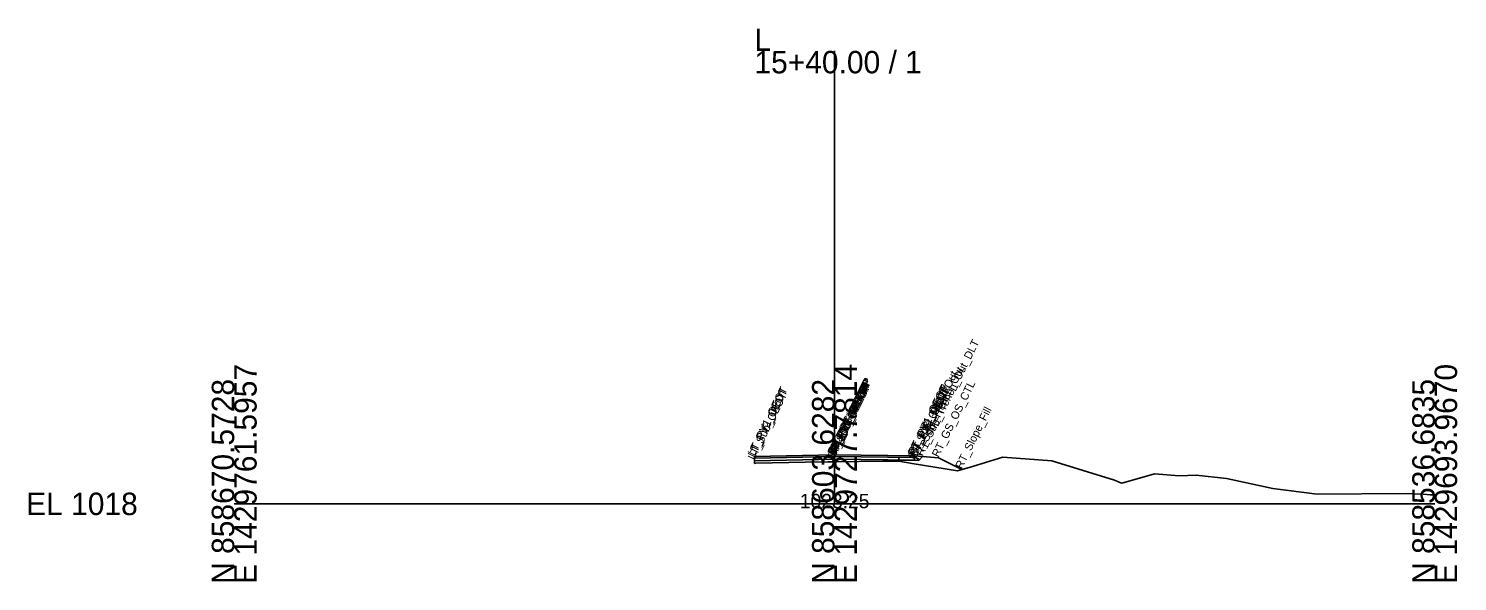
# Model space of a CAD drawing. Extents: x -26 to 2303, y -10 to 19558.
# Drawn here: x 2124.3 to 2302.8, y 5490.3 to 5559.4 of the extents above; entities that cross this region are included whole.
import ezdxf

# ---------------------------------------------------------------- set-up
doc = ezdxf.new("R2010")
doc.units = 0
for name, color, linetype in [('Default', 7, 'Continuous'), ('Exist Cross Section Cell', 7, 'Continuous'), ('Exist XS Center Line Elevation Label', 7, 'Continuous'), ('Exist XS Ground Line', 7, 'Continuous'), ('Prop CMT Conc Surface', 7, 'Continuous'), ('Prop CMT Pvmt Course 1', 7, 'Continuous'), ('Prop CMT Pvmt Course 2', 7, 'Continuous'), ('Prop CMT Pvmt Surface', 7, 'Continuous'), ('Prop CMT Pvmt Surface Shoulder', 7, 'Continuous'), ('Prop CMT Shld Paved Course 1', 7, 'Continuous'), ('Prop CMT Shld Paved Course 2', 7, 'Continuous'), ('Prop CMT Slope Grass', 7, 'Continuous'), ('Prop CMT Subgrade Earthwork', 7, 'Continuous'), ('Prop XS Dump Level', 7, 'Continuous')]:
    doc.layers.add(name, color=color, linetype=linetype)

msp = doc.modelspace()

# ---------------------------------------------------------------- linework, layer by layer
at = {"layer": 'Exist Cross Section Cell'}
for p, q in [((2225, 5500), (2225, 5556.59)), ((2150, 5500), (2225, 5500)), ((2225, 5500), (2300, 5500))]:
    msp.add_line(p, q, dxfattribs=at)
at = {"layer": 'Exist XS Ground Line'}
msp.add_lwpolyline([(2215, 5505.05), (2215.17, 5505.07), (2221.33, 5505.19), (2224.16, 5505.24), (2225, 5505.25), (2231.03, 5505.33), (2233.05, 5505.35), (2234.71, 5505.03), (2240.36, 5504.12), (2241.26, 5504.37), (2242.26, 5504.65), (2246.02, 5505.85), (2252.16, 5505.36), (2260.01, 5502.97), (2260.86, 5502.57), (2261.67, 5502.79), (2265.01, 5503.74), (2268.09, 5503.48), (2270.2, 5503.59), (2274, 5503.16), (2279.79, 5501.92), (2285.33, 5501.23), (2296.45, 5501.28), (2298.57, 5501.19), (2299.42, 5501.13), (2300, 5501.11)], dxfattribs=at)
at = {"layer": 'Prop CMT Conc Surface'}
for p, q in [((2215, 5505.39), (2215, 5505.05)), ((2233.05, 5505.35), (2233.05, 5505.81))]:
    msp.add_line(p, q, dxfattribs=at)
at = {"layer": 'Prop CMT Pvmt Course 1'}
for points in [[(2225, 5506.13), (2215, 5505.93)], [(2225, 5505.92), (2225, 5506.13)], [(2225, 5506.13), (2235, 5505.99)], [(2225, 5505.92), (2225, 5506.13)], [(2235, 5505.99), (2235, 5505.78)], [(2215, 5505.93), (2215, 5505.72)], [(2215, 5505.72), (2225, 5505.92)], [(2235, 5505.78), (2225, 5505.92)]]:
    msp.add_lwpolyline(points, dxfattribs=at)
msp.add_lwpolyline([(2225, 5505.92), (2225, 5506), (2225, 5506), (2225, 5505.92)], close=True, dxfattribs=at)
msp.add_lwpolyline([(2225, 5505.92), (2225, 5506), (2225, 5506), (2225, 5505.92)], close=True, dxfattribs=at)
at = {"layer": 'Prop CMT Pvmt Course 2'}
for points in [[(2225, 5505.92), (2215, 5505.72)], [(2215, 5505.72), (2215, 5505.39)], [(2225, 5505.92), (2235, 5505.78)], [(2235, 5505.45), (2233.05, 5505.47)], [(2235, 5505.78), (2235, 5505.45)]]:
    msp.add_lwpolyline(points, dxfattribs=at)
at = {"layer": 'Prop CMT Pvmt Surface'}
for points in [[(2225, 5506.13), (2215, 5505.93)], [(2225, 5506.13), (2235, 5505.99)]]:
    msp.add_lwpolyline(points, dxfattribs=at)
at = {"layer": 'Prop CMT Pvmt Surface Shoulder'}
msp.add_lwpolyline([(2235, 5505.99), (2235, 5505.99)], dxfattribs=at)
at = {"layer": 'Prop CMT Shld Paved Course 1'}
for points in [[(2235, 5505.99), (2235, 5505.99)], [(2235, 5505.99), (2235.21, 5505.77)], [(2235, 5505.78), (2235, 5505.99)], [(2235.21, 5505.77), (2235, 5505.78)]]:
    msp.add_lwpolyline(points, dxfattribs=at)
at = {"layer": 'Prop CMT Shld Paved Course 2'}
for points in [[(2235, 5505.78), (2235.21, 5505.77)], [(2235, 5505.45), (2235, 5505.78)], [(2235.55, 5505.43), (2235, 5505.45)], [(2235.21, 5505.77), (2235.21, 5505.77)], [(2235.21, 5505.77), (2235.55, 5505.43)]]:
    msp.add_lwpolyline(points, dxfattribs=at)
at = {"layer": 'Prop CMT Slope Grass'}
msp.add_lwpolyline([(2235, 5505.99), (2238, 5505.75), (2240.93, 5504.28)], dxfattribs=at)
at = {"layer": 'Prop CMT Subgrade Earthwork'}
for points in [[(2225, 5505.59), (2215, 5505.39)], [(2225, 5505.59), (2235, 5505.45)], [(2235, 5505.45), (2235.55, 5505.43)], [(2235.55, 5505.43), (2236.02, 5505.91)]]:
    msp.add_lwpolyline(points, dxfattribs=at)

# ---------------------------------------------------------------- texts
at = {"layer": 'Default'}
msp.add_text('-', height=0.0001, dxfattribs=at).set_placement((2150, 5500))
at = {"layer": 'Exist Cross Section Cell'}
for s, p in [('L', (2215, 5556.59)), ('15+40.00 / 1', (2215, 5553.79)), ('EL 1018', (2124, 5498.6))]:
    msp.add_text(s, height=2.8, dxfattribs=at).set_placement(p)
for s, p in [('E 1429761.5957', (2152.8, 5490)), ('E 1429727.7814', (2227.8, 5490)), ('E 1429693.9670', (2302.8, 5490)), ('N 858670.5728', (2150, 5490)), ('N 858603.6282', (2225, 5490)), ('N 858536.6835', (2300, 5490))]:
    msp.add_text(s, height=2.8, rotation=90, dxfattribs=at).set_placement(p)
at = {"layer": 'Exist XS Center Line Elevation Label'}
msp.add_text('1023.25', height=1.8, dxfattribs=at).set_placement((2220.67, 5499.45))
at = {"layer": 'Prop XS Dump Level'}
for s, p in [('RT_Sub_Trench_Out_DLT', (2236.02, 5505.91)), ('RT_Sub_Trench_Out', (2235.55, 5505.43)), ('RT_PV1_OEEOP', (2225, 5506)), ('RT_PV2_OEEOP', (2225, 5505.92)), ('LT_PV1_OEEOP', (2225, 5506)), ('LT_PV2_OEEOP', (2225, 5505.92)), ('RT_Sub_OEEOP', (2225, 5505.59)), ('RT_PV1_IEEOP', (2225, 5506)), ('RT_PV2_IEEOP', (2225, 5505.92)), ('LT_Sub_OEEOP', (2225, 5505.59)), ('LT_PV1_IEEOP', (2225, 5506)), ('LT_PV2_IEEOP', (2225, 5505.92)), ('RT_PV1_OEOT', (2235, 5505.99)), ('RT_PS1_OEOP', (2235, 5505.99)), ('RT_PS2_Shelf_Out', (2235.21, 5505.77)), ('RT_GS_OS_CTL', (2238, 5505.75)), ('LT_PV1_OEOT', (2215, 5505.93)), ('LT_PV2_OEOT', (2215, 5505.72)), ('LT_Sub_OEOT', (2215, 5505.39)), ('RT_PV2_OEOT', (2235, 5505.78)), ('RT_Sub_OEOT', (2235, 5505.45)), ('RT_PS2_OEOP', (2235.21, 5505.77)), ('PV1_PGL', (2225, 5506.13)), ('RT_Slope_Fill', (2240.93, 5504.28)), ('PV2_PGL', (2225, 5505.92))]:
    msp.add_text(s, height=1, rotation=63.5833, dxfattribs=at).set_placement(p)

doc.saveas('drawing.dxf')
